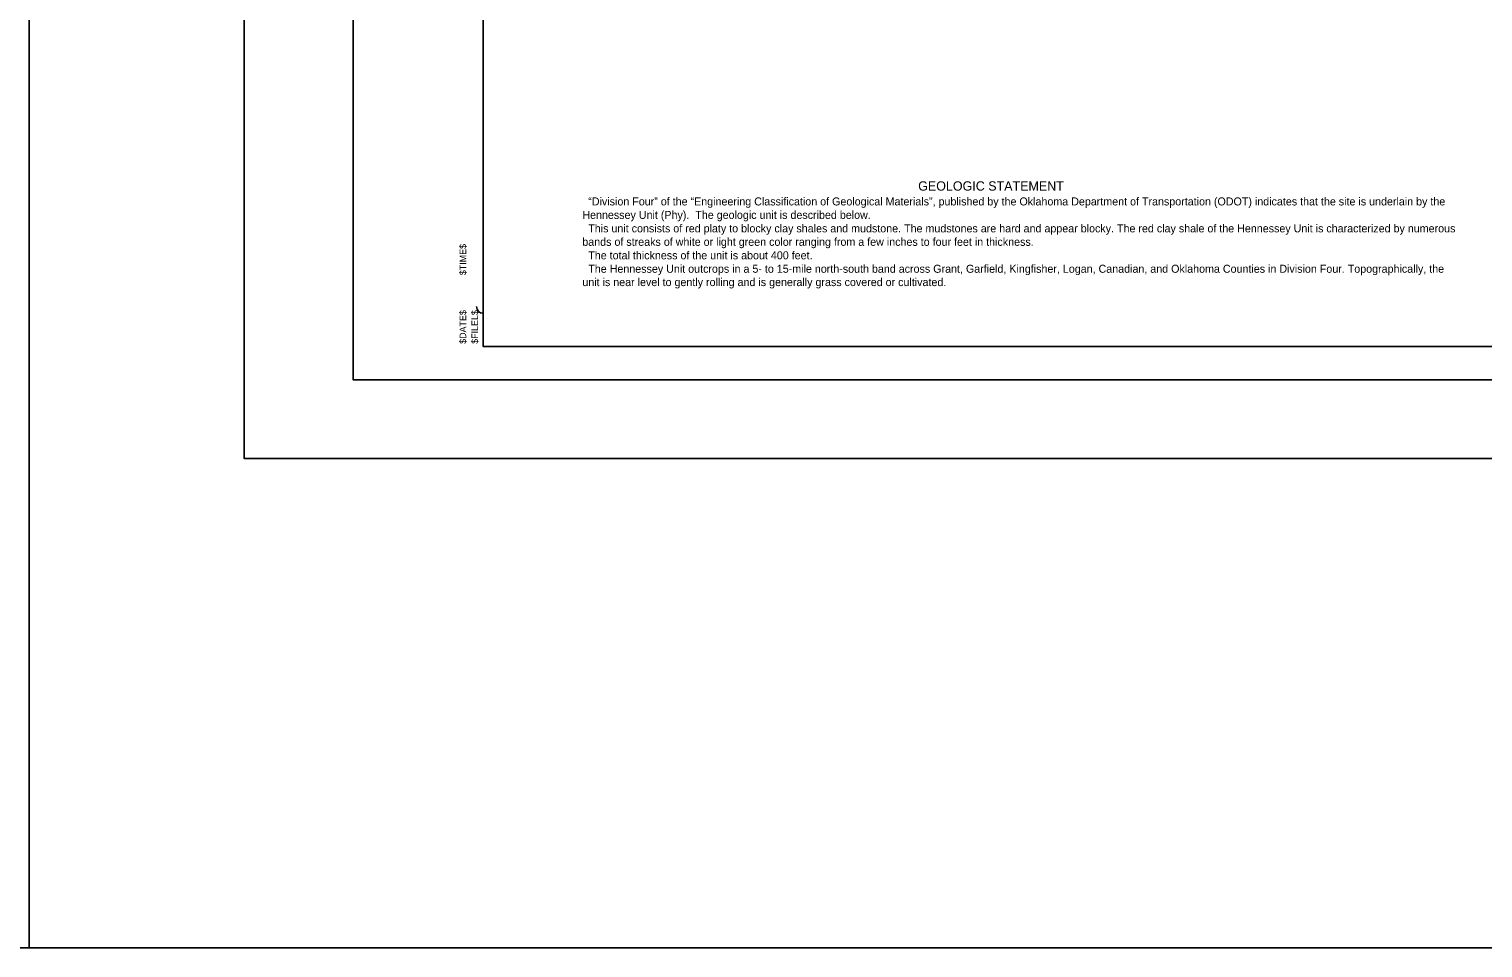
# Model space of a CAD drawing. Extents: x 2150162 to 2150245, y 143729 to 143865.
# Drawn here: x 2150203.4 to 2150225.21, y 143729.32 to 143743.1 of the extents above; entities that cross this region are included whole.
import ezdxf

# ---------------------------------------------------------------- set-up
doc = ezdxf.new("R2010")
doc.units = 0
for name, color, linetype in [('Bridge Border', 7, 'Continuous'), ('S', 7, 'Continuous'), ('SHT_Plot_Shape_Full', 7, 'Continuous'), ('SHT_Plot_Shape_Half', 7, 'Continuous'), ('SHT_Plot_Stamp', 7, 'Continuous'), ('SHT_Sheet_Border', 7, 'Continuous'), ('Text', 7, 'Continuous')]:
    doc.layers.add(name, color=color, linetype=linetype)

# ---------------------------------------------------------------- blocks, each defined once
blk = doc.blocks.new('Stamp_Plot_Stamp')
at = {"layer": 'SHT_Plot_Stamp'}
for s, p in [('$TIME$', (1.695, 1.572)), ('$DATE$', (1.695, 0.542)), ('$FILEL$', (1.873, 0.542))]:
    blk.add_text(s, height=0.1, rotation=90, dxfattribs=at).set_placement(p)

msp = doc.modelspace()

# ---------------------------------------------------------------- linework, layer by layer
at = {"layer": 'Bridge Border'}
msp.add_arc((2150210.215, 143738.935), 0.1, 180, 270, dxfattribs=at)
at = {"layer": 'S'}
for points in [[(2150203.404, 143865.061), (2150245.24, 143865.061), (2150245.24, 143729.315), (2150203.404, 143729.315)], [(2150161.568, 143784.341), (2150203.404, 143784.341), (2150203.404, 143729.315), (2150161.568, 143729.315)]]:
    msp.add_lwpolyline(points, close=True, dxfattribs=at)
at = {"layer": 'SHT_Plot_Shape_Full'}
msp.add_lwpolyline([(2150206.628, 143760.659), (2150242.628, 143760.659), (2150242.628, 143736.659), (2150206.628, 143736.659)], close=True, dxfattribs=at)
at = {"layer": 'SHT_Plot_Shape_Half'}
msp.add_lwpolyline([(2150208.265, 143759.835), (2150242.265, 143759.835), (2150242.265, 143737.835), (2150208.265, 143737.835)], close=True, dxfattribs=at)
at = {"layer": 'SHT_Sheet_Border'}
msp.add_lwpolyline([(2150241.715, 143738.335), (2150210.215, 143738.335), (2150210.215, 143759.335), (2150241.715, 143759.335)], close=True, dxfattribs=at)

# ---------------------------------------------------------------- block references
at = {"layer": 'SHT_Plot_Stamp'}
msp.add_blockref('Stamp_Plot_Stamp', (2150208.265, 143737.835), dxfattribs=at)

# ---------------------------------------------------------------- texts
at = {"layer": 'Text'}
for s, height, p in [('GEOLOGIC STATEMENT', 0.14, (2150216.738, 143740.675)), ('  “Division Four” of the “Engineering Classification of Geological Materials”, published by the Oklahoma Department of Transportation (ODOT) indicates that the site is underlain by the ', 0.12, (2150211.701, 143740.453)), ('Hennessey Unit (Phy).  The geologic unit is described below. ', 0.12, (2150211.701, 143740.251)), ('  This unit consists of red platy to blocky clay shales and mudstone. The mudstones are hard and appear blocky. The red clay shale of the Hennessey Unit is characterized by numerous ', 0.12, (2150211.701, 143740.049)), ('bands of streaks of white or light green color ranging from a few inches to four feet in thickness. ', 0.12, (2150211.701, 143739.847)), ('  The total thickness of the unit is about 400 feet.', 0.12, (2150211.701, 143739.645)), ('  The Hennessey Unit outcrops in a 5- to 15-mile north-south band across Grant, Garfield, Kingfisher, Logan, Canadian, and Oklahoma Counties in Division Four. Topographically, the ', 0.12, (2150211.701, 143739.443)), ('unit is near level to gently rolling and is generally grass covered or cultivated.', 0.12, (2150211.701, 143739.243))]:
    msp.add_text(s, height=height, dxfattribs=at).set_placement(p)

doc.saveas('drawing.dxf')
